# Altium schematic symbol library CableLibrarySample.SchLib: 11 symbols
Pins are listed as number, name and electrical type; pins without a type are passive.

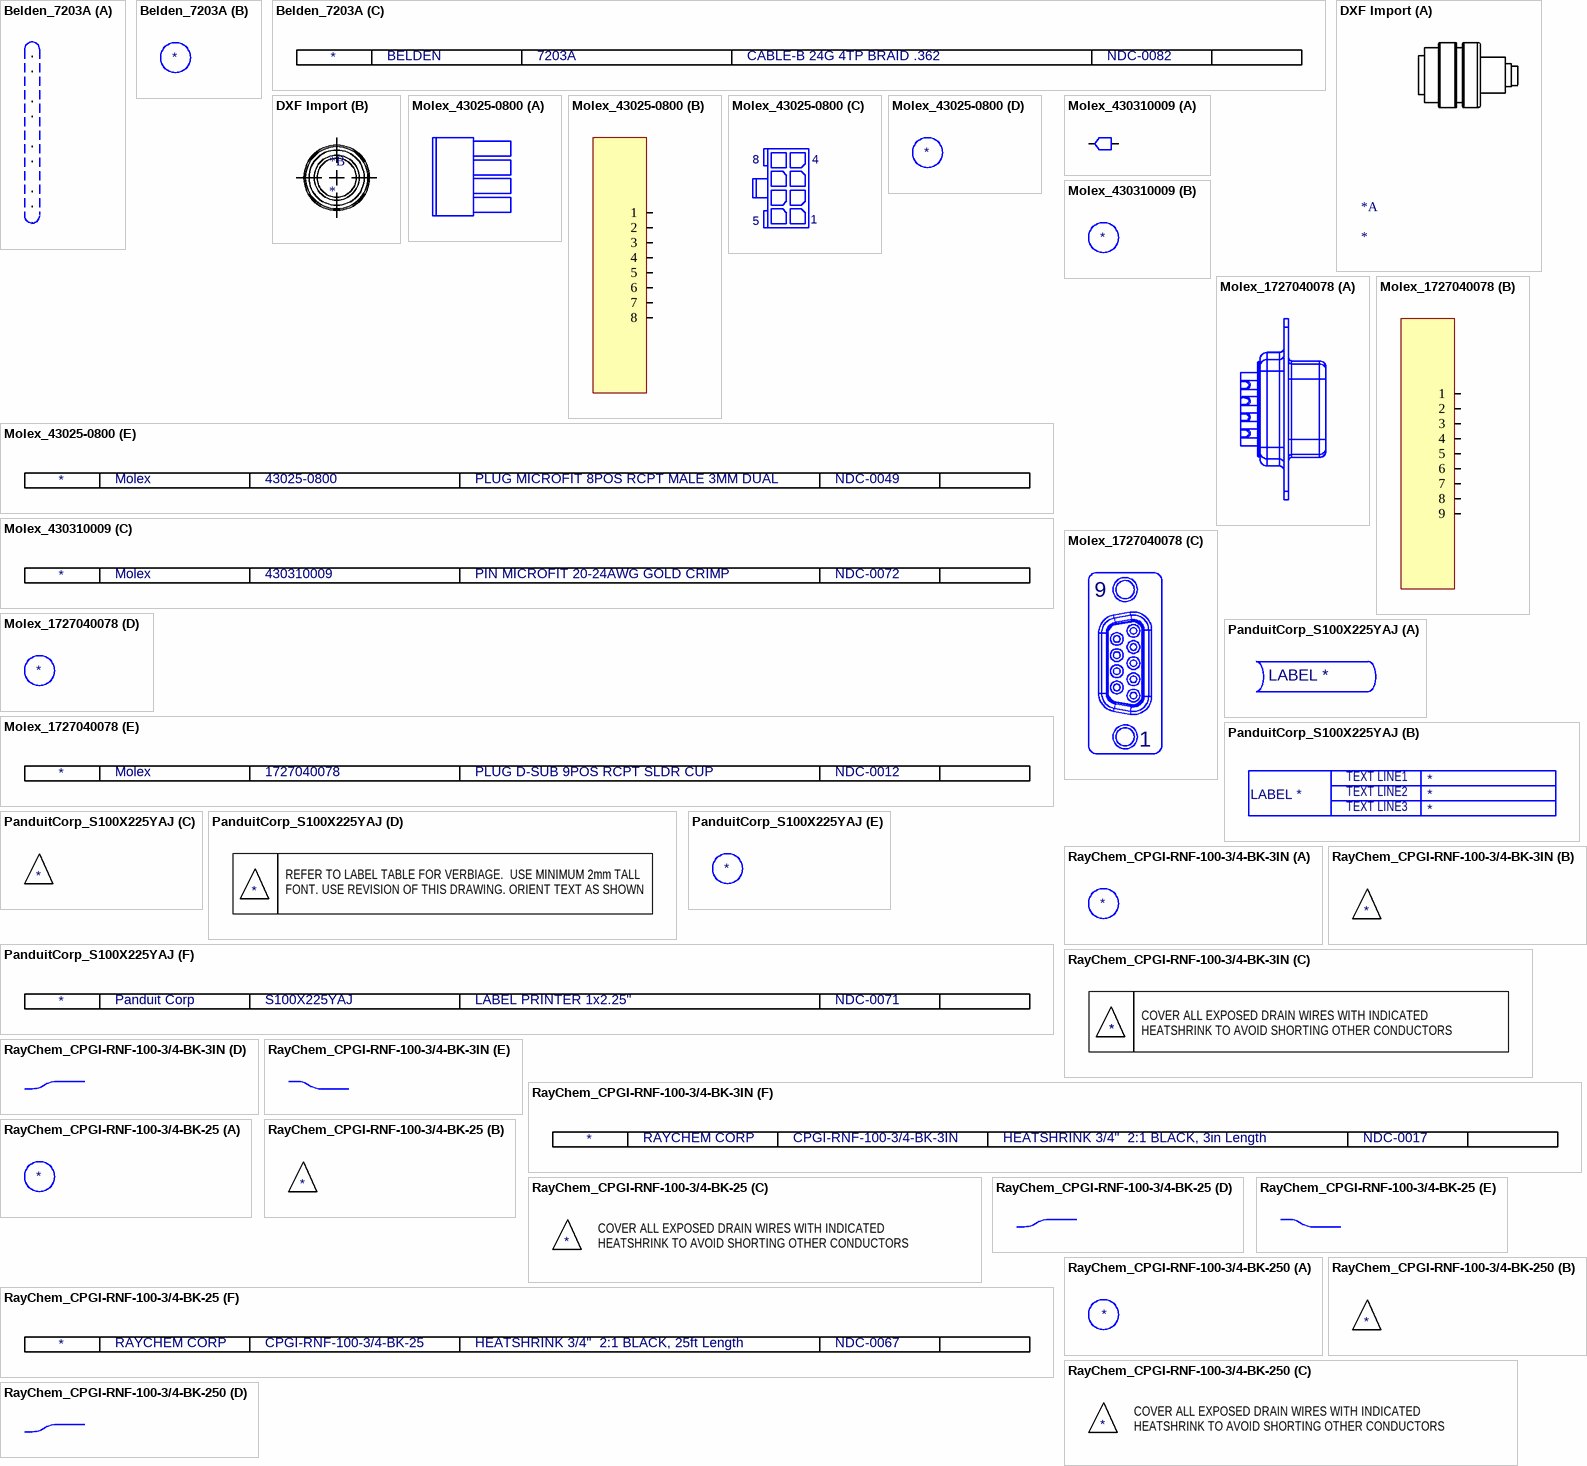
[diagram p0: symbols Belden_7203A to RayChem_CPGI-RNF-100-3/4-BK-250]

## Belden_7203A
designator W?, comment CABLE-B 24G 4TP BRAID .362  (value not drawn)
Manufacturer: BELDEN; Manufacturer PN: 7203A
part A pins: 1 BROWN, 2 WHITE1, 3 GREEN, 4 WHITE2, 5 BLUE, 6 WHITE3, 7 ORANGE, 8 WHITE4, 9 SHIELD

## DXF Import
designator *

## Molex_43025-0800
designator P?, comment PLUG MICROFIT 8POS RCPT MALE 3MM DUAL  (value not drawn)
Manufacturer: Molex; Manufacturer PN: 43025-0800; Wire Method: Solder
part B pins: 1, 2, 3, 4, 5, 6, 7, 8

## Molex_430310009
designator PIN?, comment PIN MICROFIT 20-24AWG GOLD CRIMP  (value not drawn)
Manufacturer: Molex; Manufacturer PN: 430310009
part A pins: 1, 2

## Molex_1727040078
designator P?, comment PLUG D-SUB 9POS RCPT SLDR CUP  (value not drawn)
Manufacturer: Molex; Manufacturer PN: 1727040078; Plug Type: DSUB; Wire Method: Solder
part B pins: 1, 2, 3, 4, 5, 6, 7, 8, 9

## PanduitCorp_S100X225YAJ
designator LABEL?, comment LABEL PRINTER 1x2.25"  (value not drawn)  (mechanical)
Manufacturer: Panduit Corp; Manufacturer PN: S100X225YAJ; Note Verbiage: REFER TO LABEL TABLE FOR LABELING INSTRUCTIONS.  USE MINIMUM 2mm TALL FONT. *  USE THE REVISION OF THIS DRAWING. ORIENT TEXT AS SHOWN.; Label Name: LABEL *

## RayChem_CPGI-RNF-100-3/4-BK-3IN
designator HS?, comment HEATSHRINK 3/4"  2:1 BLACK, 3in Length  (value not drawn)
Manufacturer: RAYCHEM CORP; Manufacturer PN: CPGI-RNF-100-3/4-BK-3IN

## RayChem_CPGI-RNF-100-3/4-BK-25
designator HS?, comment HEATSHRINK 3/4"  2:1 BLACK, 25ft Length  (value not drawn)
Manufacturer: RAYCHEM CORP; Manufacturer PN: CPGI-RNF-100-3/4-BK-25

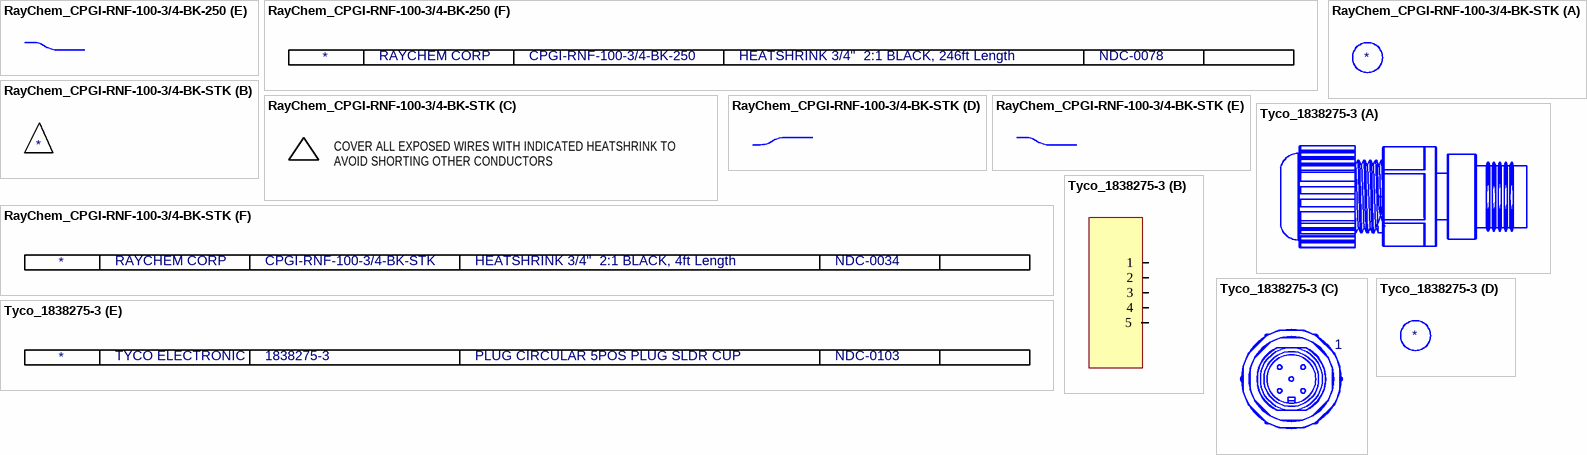
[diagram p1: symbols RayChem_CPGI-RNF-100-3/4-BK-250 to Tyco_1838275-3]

## RayChem_CPGI-RNF-100-3/4-BK-250
designator HS?, comment HEATSHRINK 3/4"  2:1 BLACK, 246ft Length  (value not drawn)
Manufacturer: RAYCHEM CORP; Manufacturer PN: CPGI-RNF-100-3/4-BK-250

## RayChem_CPGI-RNF-100-3/4-BK-STK
designator HS?, comment HEATSHRINK 3/4"  2:1 BLACK, 4ft Length  (value not drawn)
Manufacturer: RAYCHEM CORP; Manufacturer PN: CPGI-RNF-100-3/4-BK-STK

## Tyco_1838275-3
designator P?, comment PLUG CIRCULAR 5POS PLUG SLDR CUP  (value not drawn)
Manufacturer: TYCO ELECTRONIC; Manufacturer PN: 1838275-3; Wire Method: Solder
part B pins: 1, 2, 3, 4, 5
